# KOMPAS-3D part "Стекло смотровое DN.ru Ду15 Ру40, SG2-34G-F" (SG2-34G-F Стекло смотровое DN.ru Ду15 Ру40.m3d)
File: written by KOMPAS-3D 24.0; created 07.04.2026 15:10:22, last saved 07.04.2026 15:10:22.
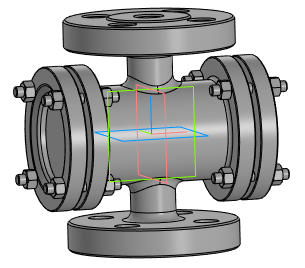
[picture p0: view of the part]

Document properties: Автор: Main; Полное имя файла: D:\DN.ru Аутсерс\Стекло смотровое DN.ru\SG2-34G-F Стекло смотровое DN.ru Ду15 Ру40\SG2-34G-F Стекло смотровое DN.ru Ду15 Ру40.m3d

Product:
- Part/product: Стекло смотровое DN.ru Ду15 Ру40  | designation SG2-34G-F
    Масса: 4
    Раздел спецификации: Прочие изделия
    Примечание: D500-00079

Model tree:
1. Операция без истории:1

Expressions: SG2-34G-F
